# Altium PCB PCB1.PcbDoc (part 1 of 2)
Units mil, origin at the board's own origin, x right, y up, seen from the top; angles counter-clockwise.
Board outline 3937.01 x 3937.01 mil, 4 copper layers (Top Layer, Int1 (PGND), Int2 (signal), Bottom Layer(AGND)), stack 43.712 mil thick; 137 components, 102 nets, 529 pads, 160 vias.
Unrouted connection lines stored in the file: 51.
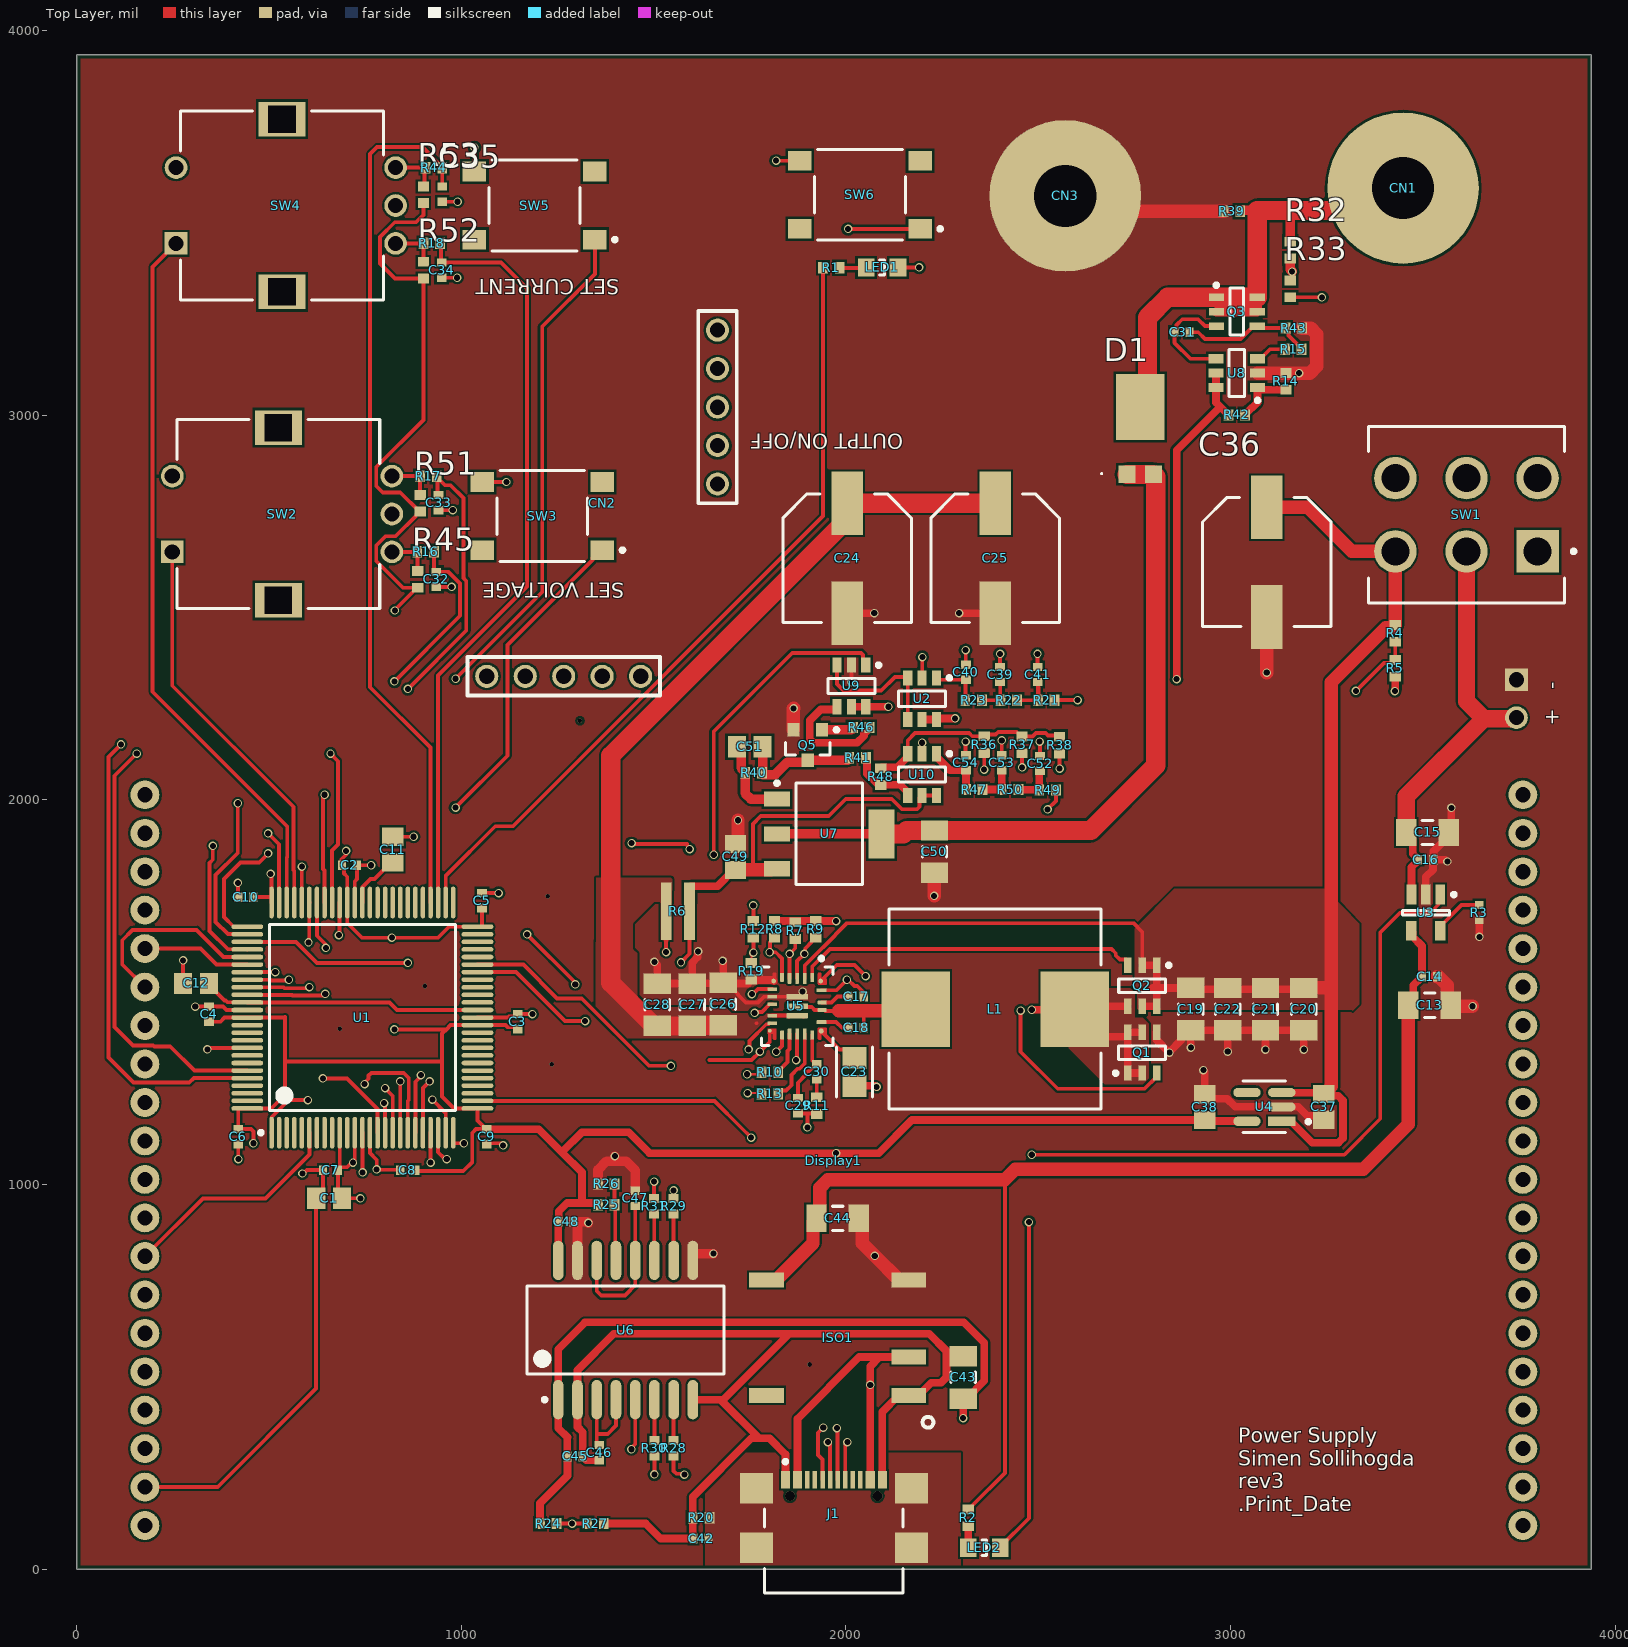
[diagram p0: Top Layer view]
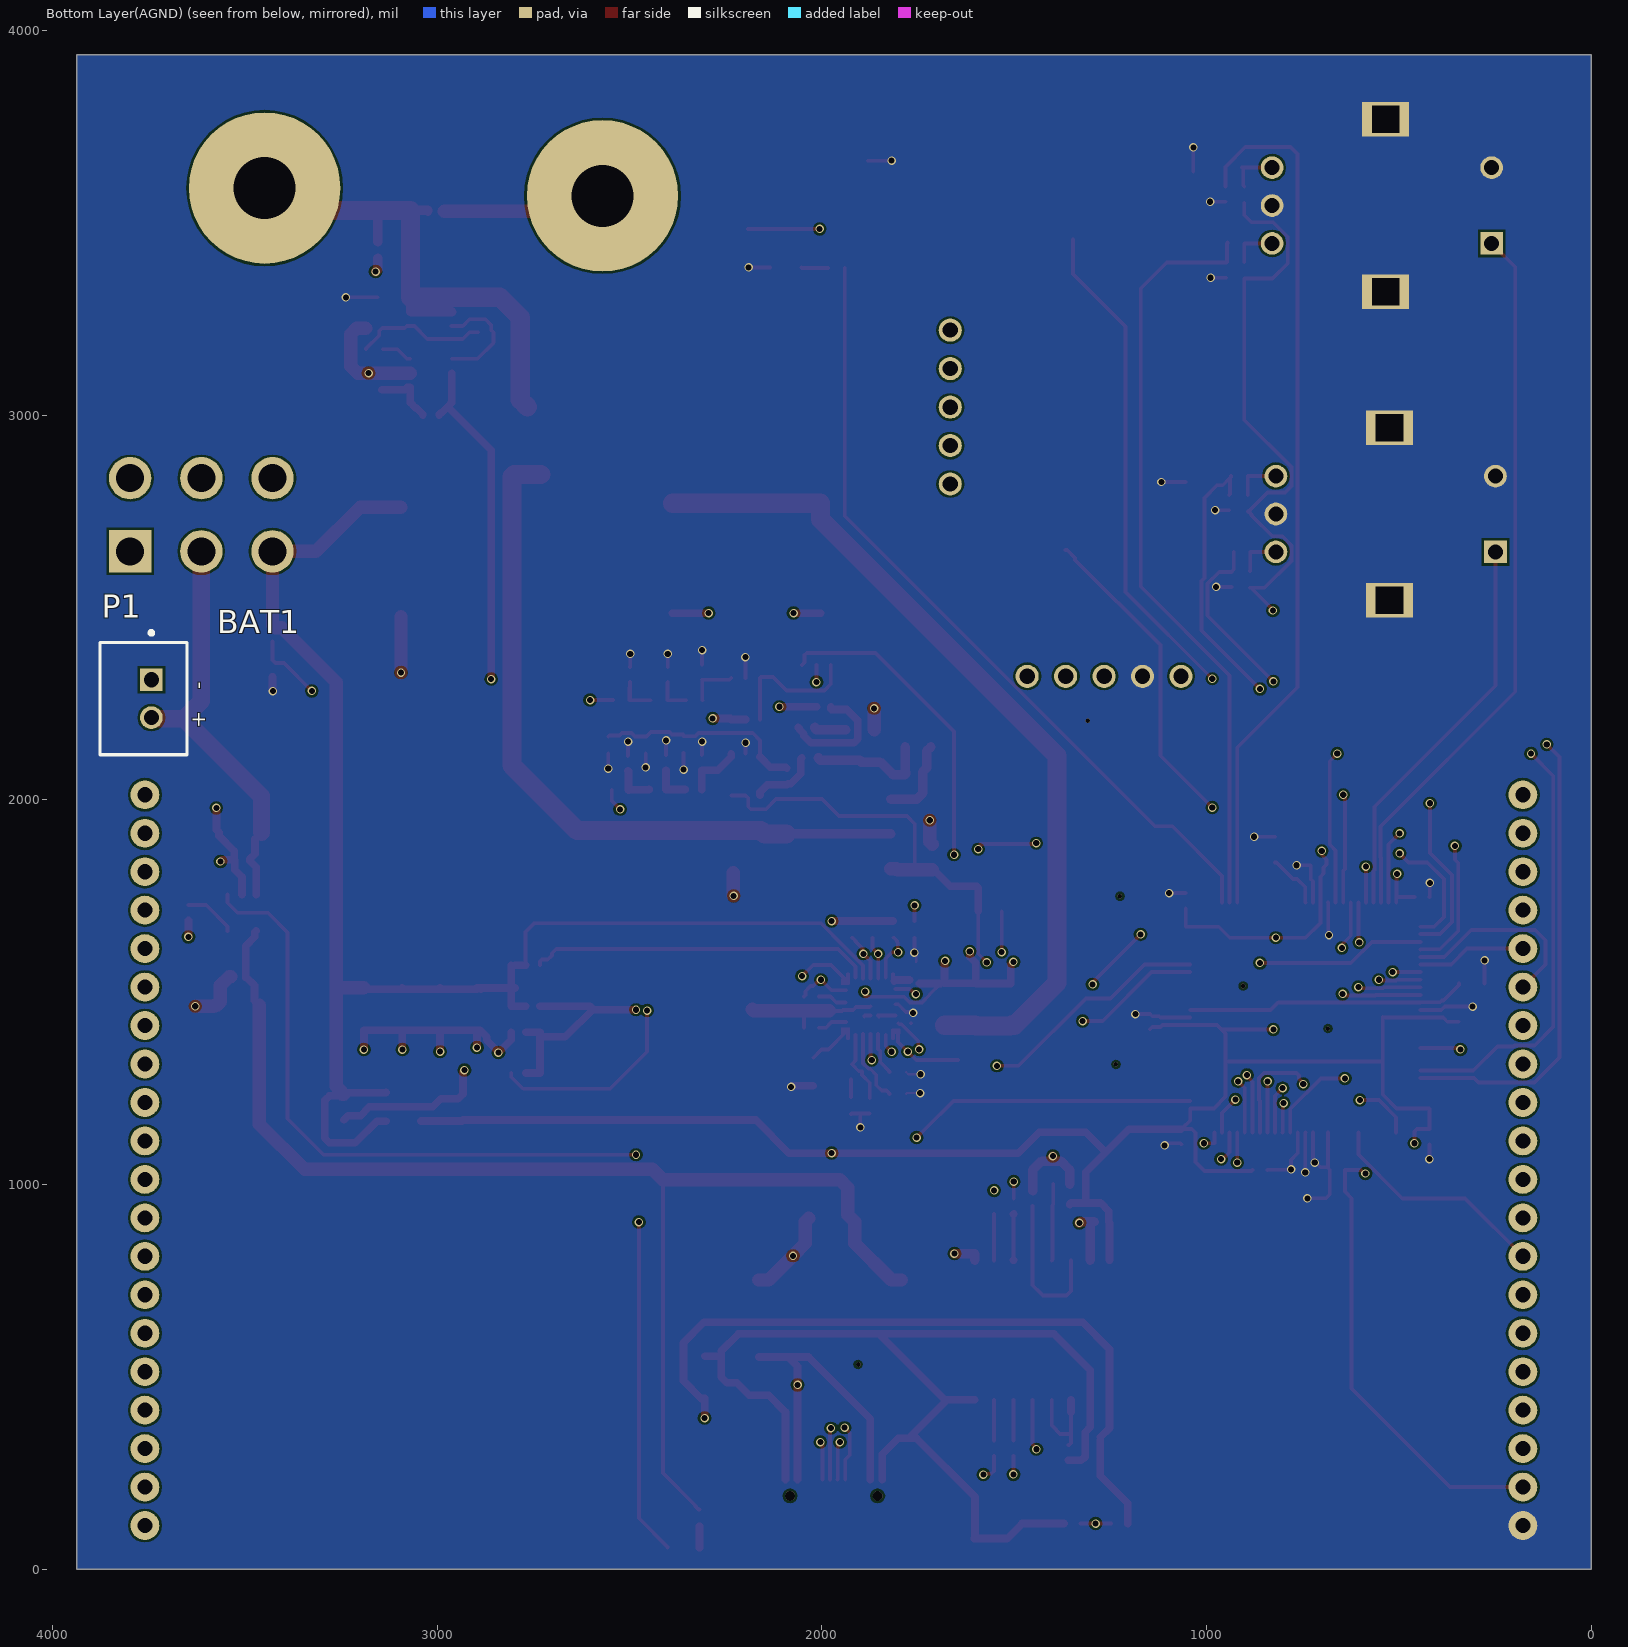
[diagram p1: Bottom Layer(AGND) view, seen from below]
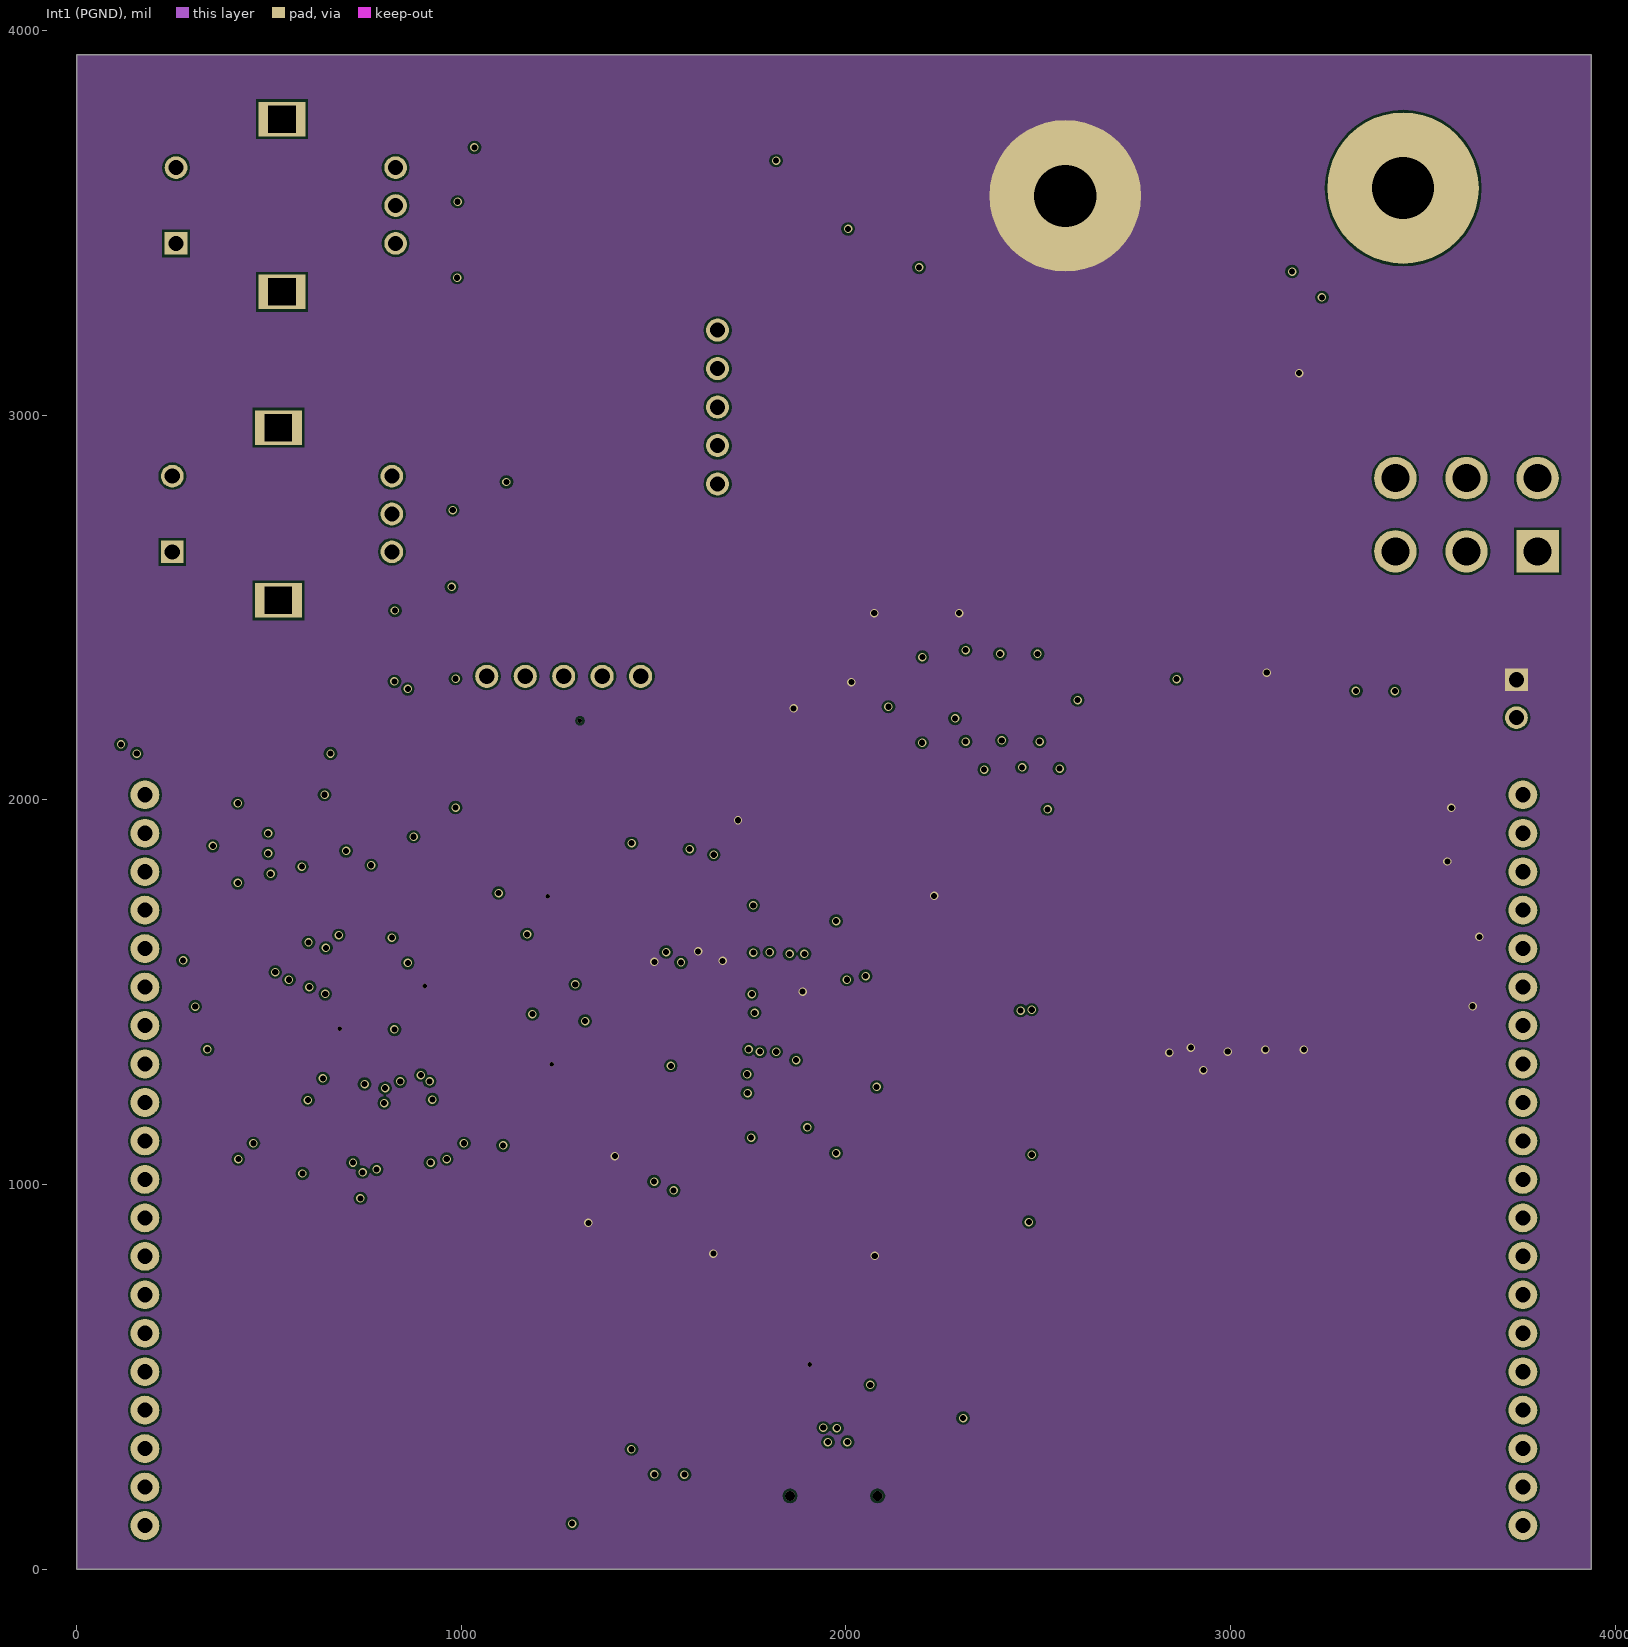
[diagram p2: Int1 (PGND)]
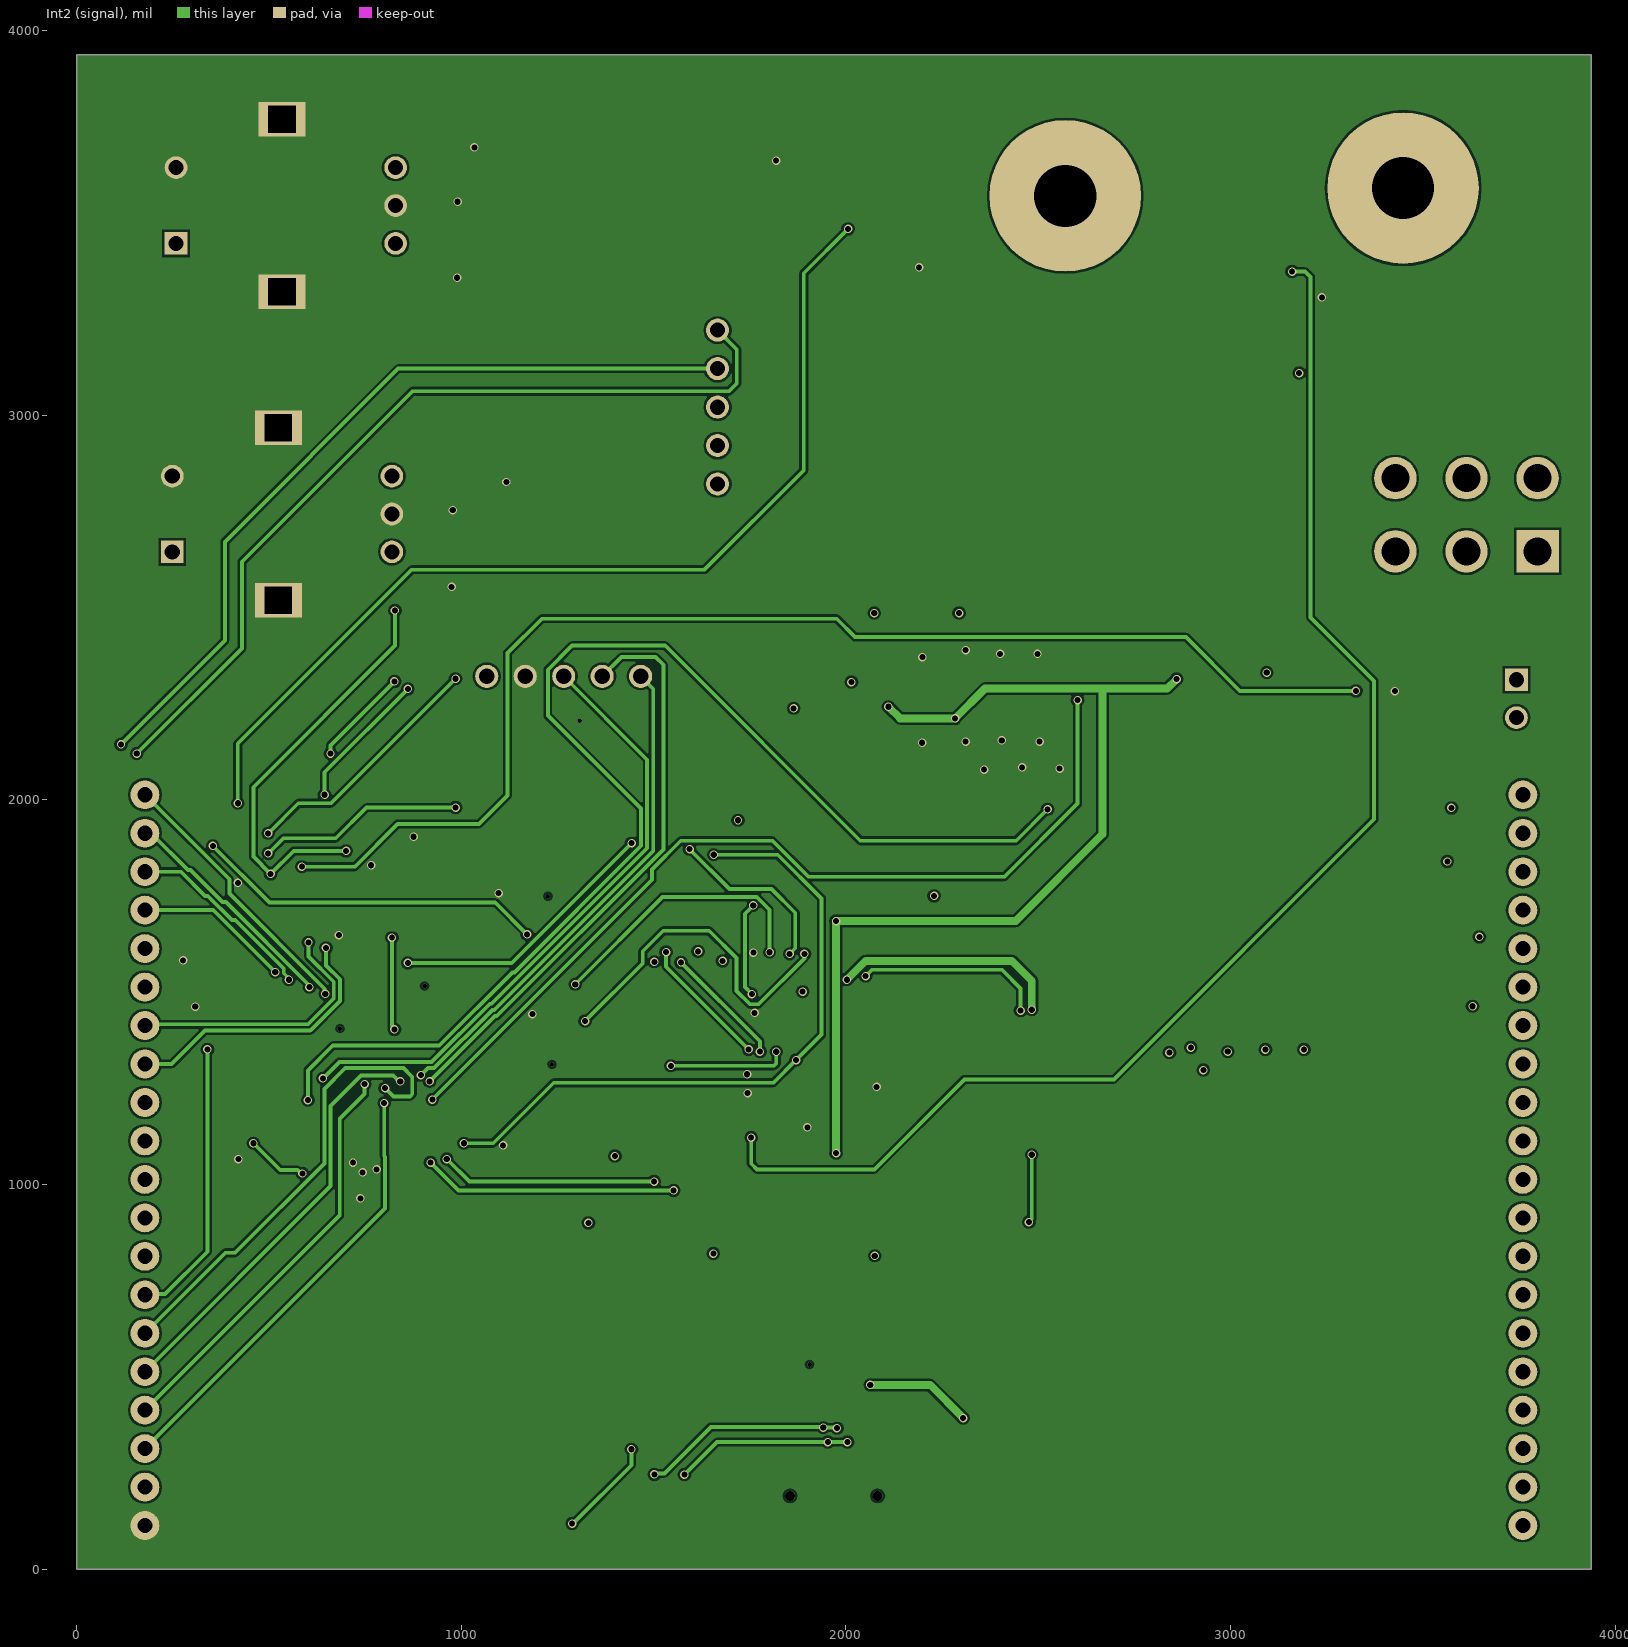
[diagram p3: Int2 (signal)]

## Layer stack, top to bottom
Top Solder: solder mask 1, SM-001, Dk 4
Top Layer: signal copper 1.378
Dielectric 2: prepreg 5.1, PP-017, Dk 4.3
Int1 (PGND): signal copper 1.378
Dielectric 3: core 28, Core-039, Dk 4.8
Int2 (signal): signal copper 1.378
Dielectric 4: prepreg 5.1, PP-017, Dk 4.3
Bottom Layer(AGND): signal copper 1.378
Bottom Solder: solder mask 1, SM-001, Dk 4

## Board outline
0,0 3937.01,0 3937.01,3937.01 0,3937.01

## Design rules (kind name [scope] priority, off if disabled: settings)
BoardOutlineClearance [(OnLayer('Bottom Layer') OR OnLayer('Top Layer') ) and not InAnyComponent] p1: gap=10 ignorepadtopadclearanceinfootprint=FALSE except(0: Arc-SplitContinuation Track-SplitContinuation SMDPad-SplitContinuation THPad-SplitContinuation Via-SplitContinuation Fill-SplitContinuation Poly-SplitContinuation Region-SplitContinuation Text-SplitContinuation; 39.37: Track-OutlineEdge SMDPad-OutlineEdge THPad-OutlineEdge Via-OutlineEdge; 118.11: Text-OutlineEdge)
Clearance [All] p1: gap=6 ignorepadtopadclearanceinfootprint=FALSE
Height [All] p1: minheight=0 maxheight=3937.01 prefheight=500
HoleSize [All] p1: absolutevalues=TRUE maxlimit=2362.2 minlimit=11.81 maxpercent=80.000 minpercent=20.000
MinimumSolderMaskSliver [not InAnyComponent] p1: minsoldermaskwidth=4
PolygonConnect [All] p1: connectstyle=Direct reliefconductorwidth=10 reliefentries=4 polygonreliefangle="90 Angle" airgapwidth=10
RoutingVias [All] p1: holewidth=15.75 width=22.05 viastyle="Through Hole" minholewidth=15.75 minwidth=22.05 maxholewidth=39.37 maxwidth=78.74
SilkToSilkClearance [All] p1 off: silktosilkclearance=10
SilkToSolderMaskClearance [IsPad] p1: minsilkscreentomaskgap=0 clearancetoexposedcopper=FALSE
SolderMaskExpansion [IsVia] p1: expansion=4 istentingtop=FALSE useseparateexpansions=TRUE expansionbottom=4 istentingbottom=TRUE
SolderMaskExpansion SolderMaskExpansion_1 [All] p2: expansion=4 istentingtop=FALSE
Width [All] p1: maxlimit=100 minlimit=6 preferedwidth=10
25 further rules are at their usual default settings.

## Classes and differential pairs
component class U_Driver: CN1 CN3 R32 R33 R36 R37 R38
component class U_usb_isolator: C43 C44 C45 C46 C47 C48 ISO1 R24 R25 R26 R27 R28 R29 R30 R31 U6
component class pta_voltage: C52 C53 C54 R47 R48 R49 R50 U10
component class pta_current: C39 C40 C41 R21 R22 R23 U2
component class U_programmer: CN2
component class U_Display: Display1
component class U_linear_regulator: C31 C49 C50 C51 D1 Q3 Q5 R14 R15 R39 R40 R41 R42 R43 R46 U7 U8 U9
component class U_mcu: C1 C2 C3 C4 C5 C6 C7 C8 C9 C10 C11 C12 LED1 R1 U1
component class U_knobs: C32 C33 C34 C35 R16 R17 R18 R44 R45 R51 R52 R53 SW2 SW3 SW4 SW5 SW6
component class U_Booster: C17 C18 C19 C20 C21 C22 C23 C24 C25 C26 C27 C28 C29 C30 C36 L1 Q1 Q2 R6 R7 R8 R8_U_Booster R9 R10 R11 R12 R13 U5
component class U_usb: C42 J1 R20
component class LDO: C37 C38 R19 U4
component class Battery: BAT1 C13 C14 C15 C16 LED2 P1 R2 R3 R4 R5 SW1 U3

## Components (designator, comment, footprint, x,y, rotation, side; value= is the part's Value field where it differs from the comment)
BAT1 "606090_4000mAH_ebay" 606090_4000mAH_ebay-Footprint-1 2401.57,1220.47 r180 bottom locked
C1 "CL21B105KBFNNNG" CAP0805 655.91,963.83 r180 top
C2 "GRM155R71H104ME14D" cap0402 709.16,1829.81 r180 top value=100nF
C3 "GRM155R71H104ME14D" cap0402 1146.33,1423 r270 top value=100nF
C4 "GRM155R71H104ME14D" cap0402 343.83,1442.68 r270 top value=100nF
C5 "GRM155R71H104ME14D" cap0402 1053.69,1737.75 r270 top value=100nF
C6 "GRM155R71H104ME14D" cap0402 420,1124 r90 top value=100nF
C7 "GRM155R71H104ME14D" cap0402 659.71,1037.13 r180 top value=100nF
C8 "GRM155R71H104ME14D" cap0402 860.73,1037.13 r0 top value=100nF
C9 "GRM155R71H104ME14D" cap0402 1066.29,1124 r90 top value=100nF
C10 "GRM155R71H104ME14D" cap0402 439.38,1746.8 r0 top value=100nF
C11 "CL21B105KBFNNNG" CAP0805 821.37,1870.36 r270 top
C12 "CL21B105KBFNNNG" CAP0805 310,1522.52 r0 top
C13 "CL31A106MBHNNNE" Chip2PinSM127P600-8N#1 3517.39,1465.54 r180 top
C14 "GRM155R71H104ME14D" cap0402 3517.39,1540.11 r180 top value=100nF
C15 "CL31A106MBHNNNE" Chip2PinSM127P600-8N#1 3512.04,1915 r180 top
C16 "GRM155R71H104ME14D" cap0402 3507.27,1843.94 r180 top value=100nF
C17 "GRM155R71H104ME14D" cap0402 2026.58,1488.36 r0 top value=100nF
C18 "GRM155R71H104ME14D" cap0402 2026.58,1407.18 r0 top value=100nF
C19 "CL31A106MBHNNNE" Chip2PinSM127P600-8N#1 2896.51,1455.66 r90 top
C20 "CL31A106MBHNNNE" Chip2PinSM127P600-8N#1 3190.4,1455.54 r90 top
C21 "CL31A106MBHNNNE" Chip2PinSM127P600-8N#1 3090.51,1455.54 r90 top
C22 "CL31A106MBHNNNE" Chip2PinSM127P600-8N#1 2992.57,1455.54 r90 top
C23 "CL21A475KAQNNNE" FP-CL21-IPC_A 2022.03,1292.61 r270 top
C24 "EEE-1HA101UP" CAPAE9983X102N 2003,2628 r270 top
C25 "EEE-1HA101UP" CAPAE9983X102N 2387.99,2628 r270 top
C26 "CL31A106MBHNNNE" Chip2PinSM127P600-8N#1 1681,1468.67 r270 top
C27 "CL31A106MBHNNNE" Chip2PinSM127P600-8N#1 1600,1467.09 r270 top
C28 "CL31A106MBHNNNE" Chip2PinSM127P600-8N#1 1509.06,1467.09 r270 top
C29 "885012005080" cap0402 1875.38,1204.68 r90 top
C30 "CC0402KRX7R9BB223" cap0402 1923.77,1292.61 r90 top
C31 "GRM155R71H104ME14D" cap0402 2873.61,3215.63 r180 top value=100nF
C32 "CC0402KRX7R9BB223" cap0402 934.92,2572.92 r90 top
C33 "CC0402KRX7R9BB223" cap0402 940.51,2772.53 r270 top
C34 "CC0402KRX7R9BB223" cap0402 948.7,3377 r90 top
C35 "CC0402KRX7R9BB223" cap0402 950.35,3574.58 r270 top
C36 "EEE-1HA101UP" CAPAE9983X102N 3094,2618 r270 top
C37 "CL21B105KBFNNNG" CAP0805 3242.26,1201.48 r90 top
C38 "CL21B105KBFNNNG" CAP0805 2933,1201 r270 top
C39 "GRM155R71H104ME14D" cap0402 2400.52,2325.67 r270 top value=100nF
C40 "GRM155R71H104ME14D" cap0402 2311.92,2331.57 r270 top value=100nF
C41 "GRM155R71H104ME14D" cap0402 2498.72,2325.67 r270 top value=100nF
C42 "GRM155R71H104ME14D" cap0402 1623.03,79.17 r0 top value=100nF
C43 "CL31A106MBHNNNE" Chip2PinSM127P600-8N#1 2304.56,498.25 r270 top
C44 "CL31A106MBHNNNE" Chip2PinSM127P600-8N#1 1978.35,911.66 r180 top
C45 "GRM155R71H104ME14D" cap0402 1295.55,292.51 r180 top value=100nF
C46 "GRM155R71H104ME14D" cap0402 1358.37,302.35 r270 top value=100nF
C47 "GRM155R71H104ME14D" cap0402 1451.87,963.64 r90 top value=100nF
C48 "GRM155R71H104ME14D" cap0402 1272.54,902.59 r0 top value=100nF
C49 "CL21B105KBFNNNG" CAP0805 1712.5,1851.22 r270 top
C50 "CL31A106MBHNNNE" Chip2PinSM127P600-8N#1 2230,1865 r90 top
C51 "CL21B105KBFNNNG" CAP0805 1749.75,2137.68 r180 top
C52 "GRM155R71H104ME14D" cap0402 2504.54,2094.26 r270 top value=100nF
C53 "GRM155R71H104ME14D" cap0402 2404.95,2096.23 r270 top value=100nF
C54 "GRM155R71H104ME14D" cap0402 2311.92,2096.23 r270 top value=100nF
CN1 "111-0702-001" 111-0702-001-Footprint-1 3448.45,3590.33 r270 top
CN2 "cy8kit-59_programer_with_uart" PR20203VBNN-Footprint-1 1266,2321 r270 top locked
CN3 "111-0703-001" 111-0702-001-Footprint-1 2570.11,3570.33 r0 top
D1 "MBR12100LPS-TP" DFN445P552X120-3N 2765,2962 r90 top
Display1 "2050" 2050-Footprint-1 1968.5,1062.99 r90 top locked
ISO1 "NXE2S0505MC-R7" NXE2S0505MC-R7-Footprint-1 1958,651 r90 top
J1 "USB4110-GF-A" FP-USB4110-GF-A-MFG 1968.5,87.6 r0 top locked
L1 "7443551730" INDP130128X65N 2387.99,1455.66 r180 top
LED1 "150080BS75000" 0805_A 2093.68,3384 r180 top
LED2 "150080BS75000" 0805_A 2359.49,55.12 r180 top
P1 "B2B-XH-A(LF)(SN)" JST-B2B-XH-A_V 3743.11,2262.71 r270 bottom locked
Q1 "PMN55ENEX" TSOP95P280X110-6N_PMN55ENE 2770,1342.55 r90 top
Q2 "PMN55ENEX" TSOP95P280X110-6N_PMN55ENE 2770.16,1516.43 r270 top
Q3 "PMN55ENEX" TSOP95P280X110-6N_PMN55ENE 3016,3269 r0 top
Q5 "MMBT3904-TP" ONSC-SOT-23-3-318-08_V 1900.47,2142.4 r270 top
R1 "RC0402FR-071KL" SMD_0402(1005)_M 1962.01,3382.88 r180 top value=1k
R2 "RC0402FR-071KL" SMD_0402(1005)_M 2318.16,132.95 r90 top value=1k
R3 "RC0402FR-072K2L" RESC1005X40X25NL05T10 3646.65,1706.35 r90 top value=2.2k
R4 "RC0402FR-0710KL" SMD_0402(1005)_M 3428.15,2432.64 r90 top value=10k
R5 "RC0402FR-0710KL" SMD_0402(1005)_M 3428.15,2341.45 r90 top value=10k
R6 "CFG0612-FX-R010ELF" Chip2PinSM127P600-8N#2 1562.7,1710.31 r180 top
R7 "RC0402FR-0710KL" SMD_0402(1005)_M 1868.08,1660.06 r90 top value=10k
R8 "RC0402FR-0710KL" SMD_0402(1005)_M 1814.21,1663.07 r90 top value=10k
R9 "RC0402FR-0710KL" SMD_0402(1005)_M 1921.8,1663.07 r90 top value=10k
R10 "RC0402FR-076K19L" RESC0402(1005)_M 1802.13,1291.57 r0 top value=6.19k
R11 "RC0402FR-0710KL" SMD_0402(1005)_M 1923.77,1204.94 r90 top value=10k
R12 "RC0402FR-0749K9L" SMD_0402(1005)_M 1759.26,1663.07 r90 top value=49.9k
R13 "RC0402FR-07100KL" SMD_0402(1005)_M 1802.13,1235.4 r180 top value=100k
R14 "RC0402FR-071KL" SMD_0402(1005)_M 3143.89,3087.66 r270 top value=1k
R15 "RC0402FR-071KL" SMD_0402(1005)_M 3163,3171.35 r180 top value=1k
R16 "RC0402FR-071KL" SMD_0402(1005)_M 907.04,2644.57 r180 top value=1k
R17 "RC0402FR-071KL" SMD_0402(1005)_M 914.25,2841.43 r180 top value=1k
R18 "RC0402FR-071KL" SMD_0402(1005)_M 923.11,3446.62 r180 top value=1k
R19 "RC0402FR-070RL" SMD_0402(1005)_M 1753.54,1554.08 r90 top value=0
R20 "RC0402FR-07100KL" SMD_0402(1005)_M 1623.03,132.95 r0 top value=100k
R21 "RC0402FR-0710KL" SMD_0402(1005)_M 2520.78,2258.74 r180 top value=10k
R22 "RC0402FR-0710KL" SMD_0402(1005)_M 2423.33,2258.74 r180 top value=10k
R23 "RC0402FR-0710KL" SMD_0402(1005)_M 2331.63,2258.74 r180 top value=10k
R24 "RC0402FR-070RL" SMD_0402(1005)_M 1226.08,118.19 r0 top value=0
R25 "RC0402FR-070RL" SMD_0402(1005)_M 1376.58,947.1 r180 top value=0
R26 "RC0402FR-07100KL" SMD_0402(1005)_M 1376.58,1001.04 r180 top value=100k
R27 "RC0402FR-07100KL" SMD_0402(1005)_M 1348.53,118.19 r180 top value=100k
R28 "RC0402FR-0724RL" RESC1005X40X25ML05T10 1551.87,314.16 r90 top
R29 "RC0402FR-0724RL" RESC1005X40X25ML05T10 1551.87,943.16 r90 top
R30 "RC0402FR-0724RL" RESC1005X40X25ML05T10 1501.87,314.16 r90 top
R31 "RC0402FR-0724RL" RESC1005X40X25ML05T10 1500.88,943.16 r90 top
R32 "RC0402FR-0710KL" SMD_0402(1005)_M 3154.72,3429.28 r90 top value=10k
R33 "RC0402FR-0710KL" SMD_0402(1005)_M 3154.72,3328.08 r90 top value=10k
R36 "RC0402FR-0710KL" SMD_0402(1005)_M 2359.37,2143.54 r90 top value=10k
R37 "RC0402FR-0710KL" SMD_0402(1005)_M 2457.78,2142.56 r90 top value=10k
R38 "RC0402FR-0710KL" SMD_0402(1005)_M 2555.23,2142.4 r90 top value=10k
R39 "RC0402FR-071KL" SMD_0402(1005)_M 3003.2,3530 r0 top value=1k
R40 "RC0402FR-071KL" SMD_0402(1005)_M 1759.59,2070.4 r180 top value=1k
R41 "RC0402FR-071KL" SMD_0402(1005)_M 2030.15,2109.17 r0 top value=1k
R42 "RC0402FR-07100KL" SMD_0402(1005)_M 3016,3000.56 r180 top value=100k
R43 "RC0402FR-0710RL" SMD_0402(1005)_M 3164.56,3226.45 r180 top value=10
R44 "RC0402FR-071KL" SMD_0402(1005)_M 928.69,3643.47 r180 top value=1k
R45 "RC0402FR-0710KL" SMD_0402(1005)_M 886.33,2572.92 r270 top value=10k
R46 "RC0402FR-071KL" SMD_0402(1005)_M 2039.89,2187.91 r0 top value=1k
R47 "RC0402FR-0710KL" SMD_0402(1005)_M 2333.57,2026.57 r180 top value=10k
R48 "RC0402FR-0710KL" SMD_0402(1005)_M 2090.68,2060.4 r270 top value=10k
R49 "RC0402FR-0710KL" SMD_0402(1005)_M 2524.22,2025.36 r180 top value=10k
R50 "RC0402FR-0710KL" SMD_0402(1005)_M 2426.6,2026.57 r180 top value=10k
R51 "RC0402FR-0710KL" SMD_0402(1005)_M 892.6,2771 r270 top value=10k
R52 "RC0402FR-0710KL" SMD_0402(1005)_M 901.45,3377 r270 top value=10k
R53 "RC0402FR-0710KL" SMD_0402(1005)_M 901.45,3572.99 r270 top value=10k
SW1 "100DP1T2B3M2QEH" FP-100DP1T2B3M2QEH-MFG 3613.19,2741 r180 top locked
SW2 "PEC11R-4215F-S0024" BOUR-PEC11R-4XXXF-SXXXX_V 524,2743 r90 top locked
SW3 "PTS645SM43SMTR92LFS" CKCP-PTS645S_V 1210.19,2737.63 r180 top
SW4 "PEC11R-4215F-S0024" BOUR-PEC11R-4XXXF-SXXXX_V 533.84,3545.05 r90 top locked
SW5 "PTS645SM43SMTR92LFS" CKCP-PTS645S_V 1190.51,3545.05 r180 top
SW6 "PTS645SM43SMTR92LFS" CKCP-PTS645S_V 2036,3573 r180 top
U1 "CY8C5867AXI-LP024" CYP-AX100_M 742.62,1433.7 r90 top
U2 "LMV341IDBVR" SOT95P280X145-6N 2197.94,2262.67 r270 top
U3 "MCP73832T-2ACI/OT" SOT-23-OT5_M 3507.54,1706.35 r270 top
U4 "TLV74333PDBVR" FP-DBV0005A-IPC_A 3087.71,1201.48 r180 top
U5 "TPS552882" FP-RPM0026A-MFG 1873,1463.28 r270 top
U6 "ADUM4160BRIZ-RL" ADI-RI-16-1_M 1426.87,621.28 r90 top
U7 "LT3080EST#TRPBF" LT-ST-3-SOT-223_M 1956.41,1911.3 r0 top
U8 "LMV341IDBVR" SOT95P280X145-6N 3016,3109.32 r180 top
U9 "LMV341IDBVR" SOT95P280X145-6N 2013.9,2296 r270 top
U10 "LMV341IDBVR" SOT95P280X145-6N 2197.94,2065.52 r270 top

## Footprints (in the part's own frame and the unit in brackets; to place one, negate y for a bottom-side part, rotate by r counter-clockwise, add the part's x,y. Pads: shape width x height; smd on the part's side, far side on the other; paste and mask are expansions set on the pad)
111-0702-001-Footprint-1 [mm]
  round 10 hole 4.1: 1(0,0)
  body extent -5.3,-5.3 5.3,5.3, height 29.51
0805_A [mm] "Chip LED, 2-Leads, Body 2.0x1.3mm, IPC Medium Density"
  rect 1.1x1.2 smd: 1(-1.05,0) 2(1.05,0)
  silkscreen extent -0.15,-0.5 0.15,0.5, body extent -1,-0.62 1,0.63, height 0.68
2050-Footprint-1 [mm]
  round 1.905 hole 1: 1(24.13,-45.5) 2(21.59,-45.5) 3(19.05,-45.5) 4(16.51,-45.5) 5(13.97,-45.5) 6(11.43,-45.5) 7(8.89,-45.5) 8(6.35,-45.5) 9(3.81,-45.5) 10(1.27,-45.5) 11(-1.27,-45.5) 12(-3.81,-45.5) 13(-6.35,-45.5) 14(-8.89,-45.5) 15(-11.43,-45.5) 16(-13.97,-45.5) 17(-16.51,-45.5) 18(-19.05,-45.5) 19(-21.59,-45.5) 20(-24.13,-45.5) 21(-24.13,45.5) 22(-21.59,45.5) 23(-19.05,45.5) 24(-16.51,45.5) 25(-13.97,45.5) 26(-11.43,45.5) 27(-8.89,45.5) 28(-6.35,45.5) 29(-3.81,45.5) 30(-1.27,45.5) 31(1.27,45.5) 32(3.81,45.5) 33(6.35,45.5) 34(8.89,45.5) 35(11.43,45.5) 36(13.97,45.5) 37(16.51,45.5) 38(19.05,45.5) 39(21.59,45.5) 40(24.13,45.5)
  body extent -33,-48 33,50, height 12
606090_4000mAH_ebay-Footprint-1 [mil]
  body extent -1180,-1180 2363,1182, height 1595
ADI-RI-16-1_M [mm] "SOIC, 16-Leads, Body 12.8x7.5mm, Pitch 1.27mm, IPC Low Density"
  oval 2.6x0.7 smd: 1(-4.6,4.445) 2(-4.6,3.175) 3(-4.6,1.905) 4(-4.6,0.635) 5(-4.6,-0.635) 6(-4.6,-1.905) 7(-4.6,-3.175) 8(-4.6,-4.445) 9(4.6,-4.445) 10(4.6,-3.175) 11(4.6,-1.905) 12(4.6,-0.635) 13(4.6,0.635) 14(4.6,1.905) 15(4.6,3.175) 16(4.6,4.445)
  silkscreen extent -4.72,-6.5 2.9,6.5, body extent -3.8,-6.5 3.8,6.5, height 2.65
BOUR-PEC11R-4XXXF-SXXXX_V [mm] "THD, 5-Leads, Body 12.5x13.4mm"
  rect 1.5x1.5 hole 1: 1(-2.5,7)
  round 1.5 hole 1: 2(2.5,7) 3(2.5,-7.5) 4(0,-7.5) 5(-2.5,-7.5)
  rect 2.3x3.1 hole 1.8 square: 6(-5.7,0) 7(5.7,0)
  silkscreen extent -6.25,-6.7 6.25,6.7, body extent -7,-7.7 7,7.2, height 21.61
cap0402 [mm] "0402 footprint for capasitors"
  rect 0.54x0.64 smd: 1(-0.5,0) 2(0.5,0)
  body extent -0.5,-0.25 0.5,0.25, height 0.5
CAP0805 [mm] "0804 smd capasitor"
  rect 1.2x1.4 smd: 1(-0.85,0) 2(0.85,0)
  body extent -1.05,-0.63 1.05,0.63, height 1.35
CAPAE9983X102N [mm] "Aluminum Electrolytic Capacitor, Body 8.30x8.30x10.20mm, IPC Medium Density"
  rect 4.2x2.1 smd: 1(-3.625,0) 2(3.625,0)
  silkscreen extent -4.25,-4.25 4.25,4.25, body extent -4.95,-4.25 4.95,4.25, height 10.2
Chip2PinSM127P600-8N#1 [mm] "1206 ceramic capasitor"
  rect 1.35x1.8 smd: 1(-1.4,0) 2(1.4,0)
  silkscreen extent -0.35,-0.8 0.35,0.8, body extent -1.7,-0.87 1.7,0.87, height 1.6
Chip2PinSM127P600-8N#2 [mm] "1206 flipped sens resitor"
  rect 0.7x3.8 smd: 1(-0.775,0) 2(0.775,0)
  body extent -0.8,-1.7 0.8,1.7, height 0.7
CKCP-PTS645S_V [mm] "THD, 4-Leads, Body 6x6mm, Pitch 4.5mm"
  rect 1.55x1.3 smd: 1(-3.975,2.25) 2(3.975,2.25) 3(-3.975,-2.25) 4(3.975,-2.25)
  silkscreen extent -5.43,-3 3,3, body extent -4.5,-3 4.5,3, height 4.3
CYP-AX100_M [mm] "QFN, 100-Leads, Body 14x14mm, Pitch 0.5mm, IPC Low Density"
  oval 2.1x0.3 smd mask+0.05: 1(-7.6,6) 2(-7.6,5.5) 3(-7.6,5) 4(-7.6,4.5) 5(-7.6,4) 6(-7.6,3.5) 7(-7.6,3) 8(-7.6,2.5) 9(-7.6,2) 10(-7.6,1.5) 11(-7.6,1) 12(-7.6,0.5) 13(-7.6,0) 14(-7.6,-0.5) 15(-7.6,-1) 16(-7.6,-1.5) 17(-7.6,-2) 18(-7.6,-2.5) 19(-7.6,-3) 20(-7.6,-3.5) 21(-7.6,-4) 22(-7.6,-4.5) 23(-7.6,-5) 24(-7.6,-5.5) 25(-7.6,-6) 51(7.6,-6) 52(7.6,-5.5) 53(7.6,-5) 54(7.6,-4.5) 55(7.6,-4) 56(7.6,-3.5) 57(7.6,-3) 58(7.6,-2.5) 59(7.6,-2) 60(7.6,-1.5) 61(7.6,-1) 62(7.6,-0.5) 63(7.6,0) 64(7.6,0.5) 65(7.6,1) 66(7.6,1.5) 67(7.6,2) 68(7.6,2.5) 69(7.6,3) 70(7.6,3.5) 71(7.6,4) 72(7.6,4.5) 73(7.6,5) 74(7.6,5.5) 75(7.6,6)
  oval 0.3x2.1 smd mask+0.05: 26(-6,-7.6) 27(-5.5,-7.6) 28(-5,-7.6) 29(-4.5,-7.6) 30(-4,-7.6) 31(-3.5,-7.6) 32(-3,-7.6) 33(-2.5,-7.6) 34(-2,-7.6) 35(-1.5,-7.6) 36(-1,-7.6) 37(-0.5,-7.6) 38(0,-7.6) 39(0.5,-7.6) 40(1,-7.6) 41(1.5,-7.6) 42(2,-7.6) 43(2.5,-7.6) 44(3,-7.6) 45(3.5,-7.6) 46(4,-7.6) 47(4.5,-7.6) 48(5,-7.6) 49(5.5,-7.6) 50(6,-7.6) 76(6,7.6) 77(5.5,7.6) 78(5,7.6) 79(4.5,7.6) 80(4,7.6) 81(3.5,7.6) 82(3,7.6) 83(2.5,7.6) 84(2,7.6) 85(1.5,7.6) 86(1,7.6) 87(0.5,7.6) 88(0,7.6) 89(-0.5,7.6) 90(-1,7.6) 91(-1.5,7.6) 92(-2,7.6) 93(-2.5,7.6) 94(-3,7.6) 95(-3.5,7.6) 96(-4,7.6) 97(-4.5,7.6) 98(-5,7.6) 99(-5.5,7.6) 100(-6,7.6)
  silkscreen extent -7.72,-6.15 6.15,6.82, body extent -7,-7 7,7, height 1.6
DFN445P552X120-3N [mm] "DFN, 3-Leads, Body 4.03x5.53mm, Pitch 4.45mm, IPC Medium Density"
  rect 4.35x3.2 smd: 1(1.5,0)
  rect 1.15x1.1 smd: 2(-2.95,-0.875) 2(-2.95,0.875)
  silkscreen extent -2.95,2.5 -2.85,2.6, body extent -3.35,-2.25 3.3,2.5, height 1.2
FP-100DP1T2B3M2QEH-MFG [mm]
  rect 2.8x2.8 hole 1.85 paste-1000 mask+0: 1(-4.7,2.415)
  round 2.8 hole 1.85 paste-1000 mask+0: 2(0,2.415) 3(4.7,2.415) 4(-4.7,-2.415) 5(0,-2.415) 6(4.7,-2.415)
  silkscreen extent -7.2,-5.84 6.48,5.84, body extent -6.58,-5.94 6.58,5.94, height 0.25
FP-CL21-IPC_A [mil]
  rect 57.27x61.27 smd paste+0 mask+0: 1(-36.45,0) 2(36.45,0)
  silkscreen extent -65,-46 65,46, body extent -85,-50 85,50, height 10
FP-DBV0005A-IPC_A [mm]
  rect 1.805x0.612 smd paste+0 mask+0: 1(-1.15,0.95)
  rrect100% 1.805x0.612 smd paste+0 mask+0: 2(-1.15,0) 3(-1.15,-0.95) 4(1.151,-0.95) 5(1.151,0.95)
  silkscreen extent -3.03,-1.7 1.4,1.7, body extent -2.55,-1.95 2.55,1.95, height 0.25
FP-RPM0026A-MFG [mm]
  round 0.306 smd paste+0 mask+0: 1(-1.661,1.555) 7(-1.661,-1.555)
  rrect40% 0.6x0.25 smd paste+0 mask+0: 2(-1.9,1) 6(-1.9,-1) 14(1.9,-1) 18(1.9,1)
  rrect40% 0.725x0.25 smd paste+0 mask+0: 3(-1.837,0.5) 4(-1.837,0) 5(-1.837,-0.5) 15(1.837,-0.5) 16(1.837,0) 17(1.837,0.5)
  rrect40% 0.25x0.625 smd paste+0 mask+0: 8(-1.125,-1.637) 9(-0.625,-1.637) 10(-0.125,-1.637) 11(0.625,-1.637) 12(1.125,-1.637)
  round 0.259 smd paste+0 mask+0: 13(1.619,-1.806)
  round 0.332 smd paste+0 mask+0: 19(1.641,1.591)
  rrect40% 0.25x0.675 smd paste+0 mask+0: 20(1.05,1.613) 23(-1.05,1.613)
  rrect40% 0.25x0.6 smd paste+0 mask+0: 21(0.25,1.65) 22(-0.25,1.65)
  rrect27% 0.375x1.425 smd paste+0 mask+0: 24(-0.625,0) 25(0,0) 26(0.625,0)
  Top Layer region: 2.15,-1.6 1.825,-1.6 1.825,-1.9 1.821,-1.919 1.81,-1.935 1.794,-1.946 1.775,-1.95 1.775,-1.95 1.525,-1.95 1.5,-1.943 1.482,-1.925 1.475,-1.9 1.475,-1.9 1.475,-1.425 1.482,-1.4 1.5,-1.382 1.525,-1.375 1.525,-1.375 2.15,-1.375 2.175,-1.382 2.193,-1.4 2.2,-1.425 2.2,-1.425 2.2,-1.55 2.196,-1.569 2.185,-1.585 2.169,-1.596 2.15,-1.6
  Top Layer region: -2.15,-1.6 -1.825,-1.6 -1.825,-1.9 -1.821,-1.919 -1.81,-1.935 -1.794,-1.946 -1.775,-1.95 -1.775,-1.95 -1.525,-1.95 -1.5,-1.943 -1.482,-1.925 -1.475,-1.9 -1.475,-1.9 -1.475,-1.425 -1.482,-1.4 -1.5,-1.382 -1.525,-1.375 -1.525,-1.375 -2.15,-1.375 -2.175,-1.382 -2.193,-1.4 -2.2,-1.425 -2.2,-1.425 -2.2,-1.55 -2.196,-1.569 -2.185,-1.585 -2.169,-1.596 -2.15,-1.6
  Top Layer region: 2.15,1.6 1.825,1.6 1.825,1.9 1.821,1.919 1.81,1.935 1.794,1.946 1.775,1.95 1.775,1.95 1.475,1.95 1.45,1.943 1.432,1.925 1.425,1.9 1.425,1.9 1.425,1.425 1.432,1.4 1.45,1.382 1.475,1.375 1.475,1.375 2.15,1.375 2.175,1.382 2.193,1.4 2.2,1.425 2.2,1.425 2.2,1.55 2.196,1.569 2.185,1.585 2.169,1.596 2.15,1.6
  Top Layer region: -2.15,1.6 -1.825,1.6 -1.825,1.9 -1.821,1.919 -1.81,1.935 -1.794,1.946 -1.775,1.95 -1.775,1.95 -1.475,1.95 -1.45,1.943 -1.432,1.925 -1.425,1.9 -1.425,1.9 -1.425,1.425 -1.432,1.4 -1.45,1.382 -1.475,1.375 -1.475,1.375 -2.15,1.375 -2.175,1.382 -2.193,1.4 -2.2,1.425 -2.2,1.425 -2.2,1.55 -2.196,1.569 -2.185,1.585 -2.169,1.596 -2.15,1.6
  silkscreen extent -3.27,-2.36 2.6,2.36, body extent -2.3,-2.05 2.3,2.05, height 0.25
FP-USB4110-GF-A-MFG [mm]
  rect 2.18x2 smd paste+0 mask+0: 1(-5.11,3.105) 2(5.11,3.105) 3(-5.11,-0.825) 4(5.11,-0.825)
  rect 0.6x1.15 smd paste+0 mask+0: A1-B12(-3.2,3.68) A4-B9(-2.4,3.68) B1-A12(3.2,3.68) B4-A9(2.4,3.68)
  rect 0.3x1.15 smd paste+0 mask+0: A5(-1.25,3.68) A6(-0.25,3.68) A7(0.25,3.68) A8(1.25,3.68) B5(1.75,3.68) B6(0.75,3.68) B7(-0.75,3.68) B8(-1.75,3.68)
  round 0.65 hole 0.65 unplated paste-1000 mask+0: ""(-2.89,2.605) ""(2.89,2.605)
  silkscreen extent -4.57,-3.83 4.57,4.99, body extent -6.3,-3.92 6.3,4.36, height 0.25
INDP130128X65N [mm] "Precision Wire Wound Inductor, 2-Leads, Body 13.00x12.75mm, IPC Medium Density"
  rect 4.5x5 smd: 1(-5.25,0) 2(5.25,0)
  silkscreen extent -7,-6.6 7,6.6, body extent -6.6,-6.38 6.6,6.38, height 6.6
JST-B2B-XH-A_V [mm] "Header, 2-Leads, Body 7.4x5.75mm, Pitch 2.5mm"
  rect 1.5x1.5 hole 1: 1(-1.25,0)
  round 1.5 hole 1: 2(1.25,0)
  silkscreen extent -4.47,-3.4 3.7,2.35, body extent -3.7,-3.4 3.7,2.35, height 7
LT-ST-3-SOT-223_M [mm] "SOT223, 4-Leads, Body 6.505x3.505mm, Pitch 2.3mm, IPC Low Density"
  rect 1.7x1 smd: 1(-3.45,2.3) 2(-3.45,0) 3(-3.45,-2.3)
  rect 1.7x3.25 smd: 4(3.45,0)
  silkscreen extent -3.57,-3.35 2.2,3.47, body extent -1.86,-3.35 1.86,3.35, height 1.8
NXE2S0505MC-R7-Footprint-1 [mm]
  rect 1x2.3 smd: 1(-5.069,-5.214) 3(-2.529,-5.214) 7(2.551,-5.214) 8(2.551,4.186) 14(-5.069,4.186)
  silkscreen extent -7.21,-6.84 -6.49,-6.13, body extent -7.61,-5.72 5.09,4.69, height 4.41
ONSC-SOT-23-3-318-08_V [mm] "SOT23, 3-Leads, Body 2.92x1.3mm, Pitch 0.95mm"
  rect 0.9x0.8 smd: 1(-1,0.95) 2(-1,-0.95) 3(1,0)
  silkscreen extent -1.12,-1.46 0.65,2.03, body extent -0.65,-1.46 0.65,1.46, height 1.11
PR20203VBNN-Footprint-1 [mil]
  round 60 hole 40: 1(0,200) 2(0,100) 3(0,0) 8(-700,400) 9(-600,400) 10(-500,400)
  round 60 hole 39.37: 4(0,-100) 5(0,-200) 6(-900,400) 7(-800,400)
  silkscreen extent -950,-250 50,450, body extent -1700,-500 100,500, height 472
RESC0402(1005)_M [mm] "Chip Resistor, Body 1.0x0.5mm, IPC Low Density"
  rect 0.65x0.75 smd: 1(-0.55,0) 2(0.55,0)
  body extent -0.52,-0.28 0.53,0.28, height 0.4
RESC1005X40X25ML05T10 [mm] "Chip Resistor, 2-Leads, Body 1.00x0.50mm, IPC Low Density"
  rect 0.6x0.65 smd: 1(-0.508,0) 2(0.508,0)
  body extent -0.53,-0.27 0.53,0.28, height 0.4
RESC1005X40X25NL05T10 [mm] "Chip Resistor, 2-Leads, Body 1.00x0.50mm, IPC Medium Density"
  rect 0.5x0.55 smd: 1(-0.508,0) 2(0.508,0)
  body extent -0.53,-0.27 0.53,0.28, height 0.4
SMD_0402(1005)_M [mm] "Chip Resistor, Body 1.0x0.5mm, IPC Low Density"
  rect 0.65x0.75 smd: 1(-0.55,0) 2(0.55,0)
  body extent -0.52,-0.28 0.53,0.28, height 0.4
SOT95P280X145-6N [mm] "SOT23, 6-Leads, Body 2.90x2.80mm, Pitch 0.95mm, IPC Medium Density"
  rect 1x0.6 smd: 1(-1.375,0.95) 2(-1.375,0) 3(-1.375,-0.95) 4(1.375,-0.95) 5(1.375,0) 6(1.375,0.95)
  silkscreen extent -1.5,-1.55 0.5,1.93, body extent -1.5,-1.53 1.5,1.53, height 1.45
SOT-23-OT5_M [mm] "SOT23, 5-Leads, Body 2.9x1.7mm, Pitch 0.95mm, Lead Span 2.8mm, IPC Low Density"
  rect 1.3x0.65 smd mask+0.05: 1(-1.2,0.95) 2(-1.2,0) 3(-1.2,-0.95)
  rect 1.3x0.7 smd: 4(1.2,-0.95) 5(1.2,0.95)
  silkscreen extent -1.32,-1.55 0.15,1.98, body extent -0.9,-1.55 0.9,1.55, height 1.45
TSOP95P280X110-6N_PMN55ENE [mm] "pin maping matches PMN55ENE- TSOP, 6-Leads, Body 2.90x1.50mm, Pitch 0.95mm, IPC Medium Density"
  rect 1x0.5 smd: 1(1.35,-0.95) 2(-1.35,0) 2(-1.35,0.95) 2(1.35,0) 2(1.35,0.95) 3(-1.35,-0.95)
  silkscreen extent -1.47,-1.55 0.45,1.87, body extent -1.38,-1.55 1.38,1.55, height 1.1

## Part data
BAT1: library part CMP-ROOT-00019-4, "https://www.ebay.com/itm/3-7V-4000-mAh-606090-Polymer-Li-battery-Li-po-For-PDA-GPS-DVD-ipod-Tablet-PC/182107148013", Capacity=4000mAh, Case/Package=606090, Voltage=3.7V
C1 C11 C12 C37 C38 C49 C51: library part CMP-0001-00012-4, "SAMSUNG ELECTRO-MECHANICS - CL21B105KBFNNNG - MLCC CAPACITORS", Capacitance=1µF, Capacitor Type=Ceramic, Case Code (Imperial)=0805, Case Code (Metric)=2012, Dielectric=X7R, Max Operating Temperature=125°C, Min Operating Temperature=-55°C, Package Quantity=3000, Tolerance=10%, Voltage=50V
C2 C3 C4 C5 C6 C7 C8 C9 C10 C14 C16 C17 C18 C31 C39 C40 C41 C42 C45 C46 C47 C48 C52 C53 C54: library part CMP-0001-00001-8, "0402 0.1 uF 50 V ±20% Tolerance X7R SMT Monolithic Ceramic Chip Capacitor", Capacitance=100nF, Capacitor Type=Ceramic, Case/Package=0402, Max Operating Temperature=125°C, Min Operating Temperature=-55°C, Tolerance=20%, Voltage Rating=50V
C13 C15 C19 C20 C21 C22 C26 C27 C28 C43 C44 C50: library part CMP-0001-00015-2, "CAP CER 10UF 50V X5R 1206", Capacitance=10µF, Capacitor Type=Ceramic, Case Code (Imperial)=1206, Case Code (Metric)=3216, Dielectric=X5R, Max Operating Temperature=85°C, Min Operating Temperature=-55°C, Tolerance=20%, Voltage Rating=50V
C23: library part CMP-0001-00018-1, "SAMSUNG ELECTRO-MECHANICS - CL21A475KAQNNNE - SMD Multilayer Ceramic Capacitor, 4.7 µF, 25 V, 0805 [2012 Metric], ± 10%, X5R, CL Series", Capacitance=4.7µF, Capacitor Type=Ceramic, Case Code (Imperial)=0805, Case Code (Metric)=2012, Dielectric=X5R, Max Operating Temperature=85°C, Min Operating Temperature=-55°C, Package Quantity=1, Tolerance=10%, Voltage Rating=25V
C24 C25 C36: library part CMP-0001-00014-2, "Cap Aluminum 100uF 50V 20% (8 X 10.2mm) SMD 200mA 2000 hr 85C T/R", Capacitance=100µF, Capacitor Type=Ceramic, Case/Package=Radial, Max Operating Temperature=85°C, Min Operating Temperature=-40°C, Package Quantity=1, Ripple Current=200mA, Tolerance=20%, Voltage Rating=50V
C29: library part CMP-0001-00010-3, "Cap, Mlcc, C0g, 100Pf, 100V, 0402", Capacitance=100pF, Capacitor Type=Ceramic, Case Code (Imperial)=0402, Case Code (Metric)=1005, Max Operating Temperature=125°C, Min Operating Temperature=-55°C, Tolerance=5%, Voltage Rating=100V
C30 C32 C33 C34 C35: library part CMP-0001-00011-3, "Multilayer Ceramic Capacitors MLCC - SMD/SMT 22K pF 10% 50 Volts", Capacitance=22nF, Capacitor Type=Ceramic, Case Code (Imperial)=0402, Case Code (Metric)=1005, Dielectric=X7R, Max Operating Temperature=125°C, Min Operating Temperature=-55°C, Package Quantity=10000, Tolerance=10%, Voltage Rating=50V
CN1: library part CMP-003-0000-1, "CONN BIND POST KNURLED RED", Color=Red, Current Rating=15A, Package Quantity=100
CN2: library part CMP-ROOT-0002-3, "CONN HDR 5POS 0.1 GOLD PCB", Color=Black, Package Quantity=1000
CN3: library part CMP-003-0001-1, "CONN BIND POST KNURLED BLACK", Color=Black, Current Rating=15A, Package Quantity=100
D1: library part CMP-ROOT-00021-1, "Diode Schottky 100V 12A TO277B", Average Rectified Current=12A, Case/Package="TO-277, 3-PowerDFN", Max Reverse Voltage (DC)=100V
Display1: library part CMP-ROOT-00015-5, "3.5\" TFT 320X480 TOUCHSCREEN", Case/Package=pcb
ISO1: library part CMP-018-0000-2, "DC DC CONVERTER 5V 2W", Case/Package=SMD/SMT, Current - Output 1=400mA, Isolation Voltage=3kV, Max Input Voltage=5.5V, Max Operating Temperature=85°C, Max Output Power=2W, Min Input Voltage=4.5V, Min Operating Temperature=-40°C, Voltage - Output 1=5V
J1: library part CMP-ROOT-00018-1, "Conn Usb 2.0 Type-c R/a SMT"
L1: library part CMP-ROOT-00003-1, "WURTH ELEKTRONIK         7443551730             Surface Mount Power Inductor, WE-HCI Series, 7.3 H, 13 A, 12 A, Shielded, 5900 ohm", Case/Package=1365, Current Rating=13A, DC Resistance (DCR)=5.9mR, Inductance=7.3uH, Inductance Tolerance=20%, Max Operating Temperature=155°C, Min Operating Temperature=-40°C, Package Quantity=400, Saturation Current=12A, Self Resonant Frequency=28MHz, Series Resistance=5.9R, Test Frequency=100kHz
LED1 LED2: library part CMP-00002-1, "SMD LED blue 3.5 V 0805, 150080BS75000, Würth Elektronik", Case Code (Imperial)=0805, Case Code (Metric)=2012, Color=Blue, Forward Current=30mA, Forward Voltage=3.2V, Max Operating Temperature=85°C, Min Operating Temperature=-40°C, Package Quantity=4000, Test Current=20mA
P1: library part CMP-ROOT-00008-1, "Conn Shrouded Header (4 Sides) HDR 2 POS 2.5mm Solder ST Thru-Hole Box", Color=Natural, Contact Resistance=20mR, Current Rating=3A, Housing Color=White, Insulation Resistance=1GR, Max Operating Temperature=85°C, Max Voltage Rating (AC)=250V, Min Operating Temperature=-25°C
Q1 Q2 Q3: library part CMP-ROOT-00001-4, "MOSFET N-CH 60V 4.5A 6TSOP", Case/Package=TSOP, Continuous Drain Current (ID)=4.5A, Drain to Source Voltage (Vdss)=60V, Input Capacitance=646pF, Max Operating Temperature=150°C, Max Power Dissipation=6.25mW, Min Operating Temperature=-55°C
Q5: library part CMP-014-0001-1, "TRANS NPN 40V 0.2A SOT23", Case/Package=SOT-23, Collector Base Voltage (VCBO)=60V, Collector Emitter Breakdown Voltage=40V, Collector Emitter Saturation Voltage=300mV, Current Rating=100mA, Emitter Base Voltage (VEBO)=6V, Frequency=300MHz, Max Collector Current=200mA, Max Operating Temperature=150°C, Max Power Dissipation=350mW, Min Operating Temperature=-55°C, Package Quantity=1
R1 R2 R14 R15 R16 R17 R18 R39 R40 R41 R44 R46: library part CMP-001-0000-7, "Surface Mount Chip Resistor, Thick Film, RC Series, 1 kohm, 62.5 mW, 1%, 50 V, 0402 [1005 Metric]", Case Code (Imperial)=0402, Case Code (Metric)=1005, Max Operating Temperature=155°C, Min Operating Temperature=-55°C, Power Rating=62.5mW, Resistance=1k, Temperature Coefficient=100ppm/°C, Tolerance=1%, Voltage Rating=50V
R3: library part CMP-001-0020-3, "RES SMD 2.2K OHM 1% 1/16W 0402", Case Code (Imperial)=0402, Case Code (Metric)=1005, Max Operating Temperature=155°C, Min Operating Temperature=-55°C, Power Rating=63mW, Resistance=2.2k, Temperature Coefficient=100ppm/°C, Tolerance=1%, Voltage Rating=50V
R4 R5 R7 R8 R9 R11 R21 R22 R23 R32 R33 R36 R37 R38 R45 R47 R48 R49 R50 R51 R52 R53: library part CMP-008-0005-9, "Surface Mount Thick Film Resistor, Rc Series, 10 Kohm, 62.5 Mw, - 1%, 50 V, 0402 [1005 Metric]", Case Code (Imperial)=0402, Case Code (Metric)=1005, Max Operating Temperature=155°C, Min Operating Temperature=-55°C, Power Rating=62.5mW, Resistance=10k, Temperature Coefficient=100ppm/°C, Tolerance=1%, Voltage Rating=50V
R6: library part CMP-0001-00016-1, "BOURNS JW MILLER - CFG0612-FX-R010ELF - SMD Current Sense Resistor, 0.01 ohm, CFG Series, 1206 Wide, 1 W, ± 1%, Metal Foil", Case/Package="Wide 1206 (3216 Metric), 0612", Resistance=10m
R10: library part CMP-0001-00019-2, "RES SMD 6.19K OHM 1% 1/16W 0402", Case Code (Imperial)=0402, Case Code (Metric)=1005, Max Operating Temperature=155°C, Min Operating Temperature=-55°C, Power Rating=62.5mW, Resistance=6.19k, Resistor Type="Thick Film", Temperature Coefficient=100ppm/°C, Tolerance=1%, Voltage Rating=50V
R12: library part CMP-0001-00013-2, "Res Thick Film 0402 49.9K Ohm 1% 0.063W(1/16W) ±100ppm/C Epoxy Pad SMD T/R", Case Code (Imperial)=0402, Case Code (Metric)=1005, Max Operating Temperature=155°C, Min Operating Temperature=-55°C, Power Rating=62.5mW, Resistance=49.9k, Temperature Coefficient=100ppm/°C, Tolerance=1%, Voltage Rating=50V
R13 R20 R26 R27 R42: library part CMP-0001-00006-4, "Res General Purpose Thick Film 0402 100K Ohm 1% 1/16W ±100ppm/°C Molded SMD Paper T/R", Case Code (Imperial)=0402, Case Code (Metric)=1005, Max Operating Temperature=155°C, Max Power Dissipation=63mW, Min Operating Temperature=-55°C, Package Quantity=1, Resistance=100k, Temperature Coefficient=100ppm/°C, Tolerance=1%, Voltage Rating=50V
R19 R24 R25: library part CMP-0001-00005-6, "Res Thick Film 0402 0 Ohm Molded SMD SMD Paper T/R", Case Code (Imperial)=0402, Case Code (Metric)=1005, Max Operating Temperature=155°C, Min Operating Temperature=-55°C, Power Rating=62.5mW, Resistance=0, Temperature Coefficient=200ppm/°C, Tolerance=1%, Voltage Rating=50V
R28 R29 R30 R31: library part CMP-0001-00017-2, "Thick Film Resistors 24 OHM 1%", Case Code (Imperial)=0402, Case Code (Metric)=1005, Max Operating Temperature=155°C, Max Power Dissipation=63mW, Min Operating Temperature=-55°C, Resistance=24, Temperature Coefficient=100ppm/°C, Tolerance=1%, Voltage Rating=50V
R43: library part CMP-0001-00007-3, "RES SMD 10 OHM 1% 1/16W 0402", Case Code (Imperial)=0402, Case Code (Metric)=1005, Max Operating Temperature=155°C, Min Operating Temperature=-55°C, Power Rating=63mW, Resistance=10, Temperature Coefficient=100ppm/°C, Tolerance=1%, Voltage Rating=50V
SW1: library part CMP-ROOT-00014-1, "100 Series DPDT On-None-On Through Hole Miniature Toggle Switch", Case/Package=dip, Current Rating=5A, Max Operating Temperature=85°C, Min Operating Temperature=-30°C, Package Quantity=200, Voltage Rating (AC)=120V, Voltage Rating (DC)=28V
SW2 SW4: library part CMP-ROOT-00012-1, "BOURNS - PEC11R-4215F-S0024 - Rotary Encoder, Mechanical, Incremental, 24 PPR, 24 Detents, Vertical, With Momentary Push Switch", Case/Package=encoder, Max Operating Temperature=70°C, Min Operating Temperature=-30°C, Package Quantity=150
SW3 SW5 SW6: library part CMP-ROOT-00020-1, Case/Package=smd
U1: library part CMP-00001-4, "IC MCU 32BIT 128KB FLASH 100TQFP", Case/Package=TQFP, Frequency=67MHz, Max Operating Temperature=85°C, Max Supply Voltage=5.5V, Min Operating Temperature=-40°C, Min Supply Voltage=1.71V, Package Quantity=1
U2 U8 U9 U10: library part CMP-ROOT-00000-2, "Single Rail-To-Rail Output CMOS Operational Amplifier with Shutdown 6-SOT-23 -40 to 125", Case/Package=SOT-23, Input Bias Current=200pA, Input Offset Voltage (Vos)=250uV, Max Frequency=1kHz, Max Operating Temperature=125°C, Max Supply Voltage=5.5V, Min Operating Temperature=-40°C, Min Supply Voltage=2.5V, Nominal Supply Current=170uA, Operating Supply Current=107uA, Output Current=32mA, Output Current per Channel=113mA, Package Quantity=1, Voltage Gain=116dB
U3: library part CMP-006-0003-2, "BATTERY CHARGER, 500mA, SOT23-5; Battery Type:Li-Ion, Li-Pol; Input Voltage:6V; Battery Charge Voltage:4.2V; Charge Current Max:500mA; Battery IC Case Style:SOT-23; No. of Pins:5; No. of Series Cells:1; Operating Temperature Max:85 C", Case/Package=SOT-23, Max Charge Current=500mA, Max Input Voltage=6V, Max Operating Temperature=85°C, Max Output Voltage=4.5V, Max Power Dissipation=1.54W, Min Operating Temperature=-40°C, Min Output Voltage=4.168V, Min Supply Voltage=3.75V, Output Current=10mA, Output Voltage=4.2V, Package Quantity=3000
U4: library part CMP-00004-1, "300mA Low-Dropout (LDO) Regulator 5-SOT-23 -40 to 125", Case/Package=SOT-23-5, Dropout Voltage=270mV, Max Input Voltage=5.5V, Max Operating Temperature=125°C, Min Operating Temperature=-40°C, Min Output Voltage=3.3V, Output Current=300mA, Power Supply Rejection Ratio (PSRR)=28dB, Quiescent Current=60uA
U5: library part CMP-00006-4, "36V, 16A buck-boost converter with PPS control"
U6: library part CMP-00003-5, "Digital Isolator CMOS 4-CH 12Mbps 16-Pin SOIC T/R", Case/Package=SOIC, Isolated Power=No, Max Operating Temperature=105°C, Max Supply Voltage=5.5V, Min Operating Temperature=-40°C, Min Supply Voltage=3.1V, Nominal Supply Current=6mA, Package Quantity=1000
U7: library part CMP-00005-1, "IC REG LIN POS ADJ 1.1A SOT223-3", Case/Package=SOT-223, Dropout Voltage=1.35V, Max Input Voltage=36V, Max Operating Temperature=125°C, Min Current Limit=1.1A, Min Input Voltage=1.2V, Min Operating Temperature=-40°C, Operating Supply Current=300uA, Output Voltage Accuracy=1%, Package Quantity=1, Quiescent Current=500uA

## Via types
v1: diameter 22.05, hole 15.75, Top Layer to Bottom Layer(AGND), tented bottom, 154 vias
v2: diameter 11.81, hole 11.81, Top Layer to Bottom Layer(AGND), tented bottom, 6 vias

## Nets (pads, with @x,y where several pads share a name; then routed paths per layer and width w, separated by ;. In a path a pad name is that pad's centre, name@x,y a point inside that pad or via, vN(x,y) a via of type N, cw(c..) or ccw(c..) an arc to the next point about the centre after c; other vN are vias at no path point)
3V3: C1.2 C2.2 C3.2 C4.2 C5.2 C6.2 C7.2 C8.2 C9.2 C10.2 C38.2 C48.1 Display1.22 R7.2 R8.2 R9.2 R25.2 R42.2 R45.2 R51.2 R52.2 R53.2 U1.26 U1.37 U1.50 U1.65 U1.75 U1.88 U1.100 U2.5 U2.6 U4.5 U6.16 U8.5 U8.6 U9.5 U9.6 | length 13216.5
  Top Layer w10: Display1.22@177.17,212.99 366.54,212.99 622.44,468.9 C1.2@622.44,963.83 640.02,981.41 C7.2@640.02,1037.13 598.72,1037.13 589.91,1028.31 v1(586.65,1028.31) ; C4.2@343.83,1423 373.63,1423 384.33,1433.7 U1.88@443.41,1433.7 540.49,1433.7 541.6,1434.81 541.6,1319.33 ; v1(459.06,1107.03) 459.06,1137.83 453.2,1143.69 C6.2@420,1143.69 420,1196.64 420.84,1197.48 U1.100@443.41,1197.48 505.69,1197.48 541.6,1233.39 541.6,1319.33 ; C10.2@459.06,1746.8 505.57,1746.8 U1.75@506.06,1746.31 ; v1(504.07,1807.09) 506.06,1805.09 U1.75@506.06,1746.31 ; U1.75@506.4,1732.91 506.4,1745.97 U1.75@506.06,1746.31 ; v1(700.1,1867.19) 700.1,1857.01 687.69,1844.59 687.69,1831.6 695.1,1824.18 695.1,1808.1 703.25,1799.95 U1.65@703.25,1732.91 703.25,1680 741.85,1641.41 v1(819.28,1641.41) 939.28,1641.41 967.79,1669.92 U1.50@1041.84,1669.92 1052.86,1669.92 1053.69,1670.76 C5.2@1053.69,1718.06 ; v1(826.03,1402.99) 961.04,1402.99 ; v1(827.15,2492.09) 827.15,2494.06 R45.2@884.36,2551.27 ; C8.2@880.42,1037.13 882.8,1034.75 1004.98,1034.75 1028.43,1058.19 1028.43,1134.21 1037.9,1143.69 C9.2@1064.32,1143.69 ; R45.2@886.33,2551.27 R45.2@884.36,2551.27 ; R51.2@892.6,2749.35 R51.2@890.63,2749.35 ; R53.2@901.45,3551.34 901.45,3520.66 882.4,3501.61 826.79,3501.61 788.59,3463.41 788.59,3394.43 827.67,3355.35 R52.2@901.45,3355.35 901.45,2987.62 778.75,2864.91 778.75,2815.73 795.43,2799.05 840.92,2799.05 R51.2@890.63,2749.35 ; C9.2@1066.29,1143.69 C9.2@1064.32,1143.69 ; C3.2@1146.33,1403.31 1140.7,1408.94 1119.45,1408.94 1114.38,1414.02 U1.37@1041.84,1414.02 972.07,1414.02 961.04,1402.99 ; 541.6,1319.33 947.62,1319.33 950.02,1321.73 ; R45.2@884.36,2551.27 848.57,2551.27 778.75,2621.09 778.75,2661.36 802.49,2685.1 828.35,2685.1 882.83,2739.58 882.83,2741.55 R51.2@890.63,2749.35 ; 950.02,1321.73 950.02,1391.97 961.04,1402.99 ; 950.02,1321.73 950.02,1228.03 980.58,1197.48 U1.26@1041.84,1197.48 1041.84,1166.17 C9.2@1064.32,1143.69
  Top Layer w20: C9.2@1066.29,1143.69 1201.33,1143.69 1261.38,1083.63 ; U6.16@1251.87,802.39 1251.87,899.63 1252.86,900.62 C48.1@1252.86,902.59 1253.49,903.22 1253.49,930.17 1275.15,951.83 1313.64,951.83 ; R25.2@1354.92,947.1 1354.92,949.03 1352.13,951.83 1313.64,951.83 ; R8.2@1814.21,1684.72 1868.08,1684.72 R9.2@1921.81,1684.72 v1(1974.24,1684.72) ; v1(1974.24,1081.51) v1@1974.41,1081.34 ; U9.5@2013.9,2241.87 U9.6@2051.3,2241.87 v1(2110.29,2241.87) ; U2.5@2197.94,2208.54 U2.6@2235.35,2208.54 2235.35,2209.33 2237.16,2211.14 2283.27,2211.14 v1(2283.66,2211.53) ; v1(2859.55,2313.85) 2859.55,2909.07 2972.69,3022.21 ; U8.5@2961.87,3109.32 U8.6@2961.87,3071.92 2961.87,3033.04 2972.69,3022.21 ; R42.2@2994.35,3000.56 2994.35,3002.53 2991.55,3005.32 2989.58,3005.32 2972.69,3022.21 ; U4.5@3042.42,1164.08 3041.63,1164.86 2935.67,1164.86 C38.2@2933,1167.53 2171.53,1167.53 2085.34,1081.34 v1@1974.41,1081.34 ; 1261.38,1083.63 1313.64,1031.38 1313.64,951.83 ; 1261.38,1083.63 1313.56,1135.81 1434.75,1135.81 1489.22,1081.34 v1@1974.41,1081.34
  Int2 (signal) w10: v1(459.06,1107.03) 528.96,1037.13 574.58,1037.13 583.39,1028.31 v1(586.65,1028.31) ; v1(700.1,1867.19) 564.17,1867.19 v1(504.07,1807.09) 459.06,1852.09 459.06,2032.61 827.15,2400.69 v1(827.15,2492.09) ; v1(819.28,1641.41) 819.28,1413.01 826.03,1406.25 v1(826.03,1402.99)
  Int2 (signal) w20: v1(1974.24,1081.51) v1(1974.24,1684.72) 2441.05,1684.72 2666.68,1910.34 2666.68,2289.22 ; v1(2110.29,2241.87) 2140.62,2211.53 v1(2283.66,2211.53) 2361.35,2289.22 2666.68,2289.22 ; v1(2859.55,2313.85) 2834.92,2289.22 2666.68,2289.22
5V: C13.2 C14.2 C44.2 ISO1.8 R2.2 U3.4 | length 3338.4
  Top Layer w10: R2.2@2318.15,154.61 2320.12,154.61 2327.92,162.4 2327.92,164.37 2413,249.45 2413,1011.87
  Top Layer w20: C13.2@3462.27,1465.55 3474.92,1478.2 3474.92,1517.33 3495.1,1537.51 3497.07,1537.51 3497.7,1538.14 C14.2@3497.7,1540.11 3497.7,1619.73 3473.92,1643.51 3473.92,1655.32 U3.4@3470.14,1659.1
  Top Layer w35: ISO1.8@1793.19,751.44 1818.78,751.44 1914.15,846.81 1914.15,902.59 C44.2@1923.23,911.66 1932.3,920.74 1932.3,991.37 1952.81,1011.87 2413,1011.87 2440.11,1038.98 3344.61,1038.98 3462.27,1156.63 C13.2@3462.27,1465.55
BAT+: C15.2 C16.2 P1.2 SW1.2 U3.3 | length 1100.2
  Top Layer w20: C15.2@3456.92,1915 3473.5,1898.43 3473.5,1860 3487.58,1845.91 C16.2@3487.58,1843.94 3487.58,1841.97 3470.14,1824.53 U3.3@3470.14,1753.59
  Top Layer w45: C15.2@3456.92,1915 3456.92,2008.85 3658.88,2210.81 ; SW1.2@3613.19,2645.92 3613.19,2256.5 3658.88,2210.81 ; P1.2@3743.11,2213.5 3740.42,2210.81 3658.88,2210.81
